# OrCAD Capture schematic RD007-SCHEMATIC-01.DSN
size A3
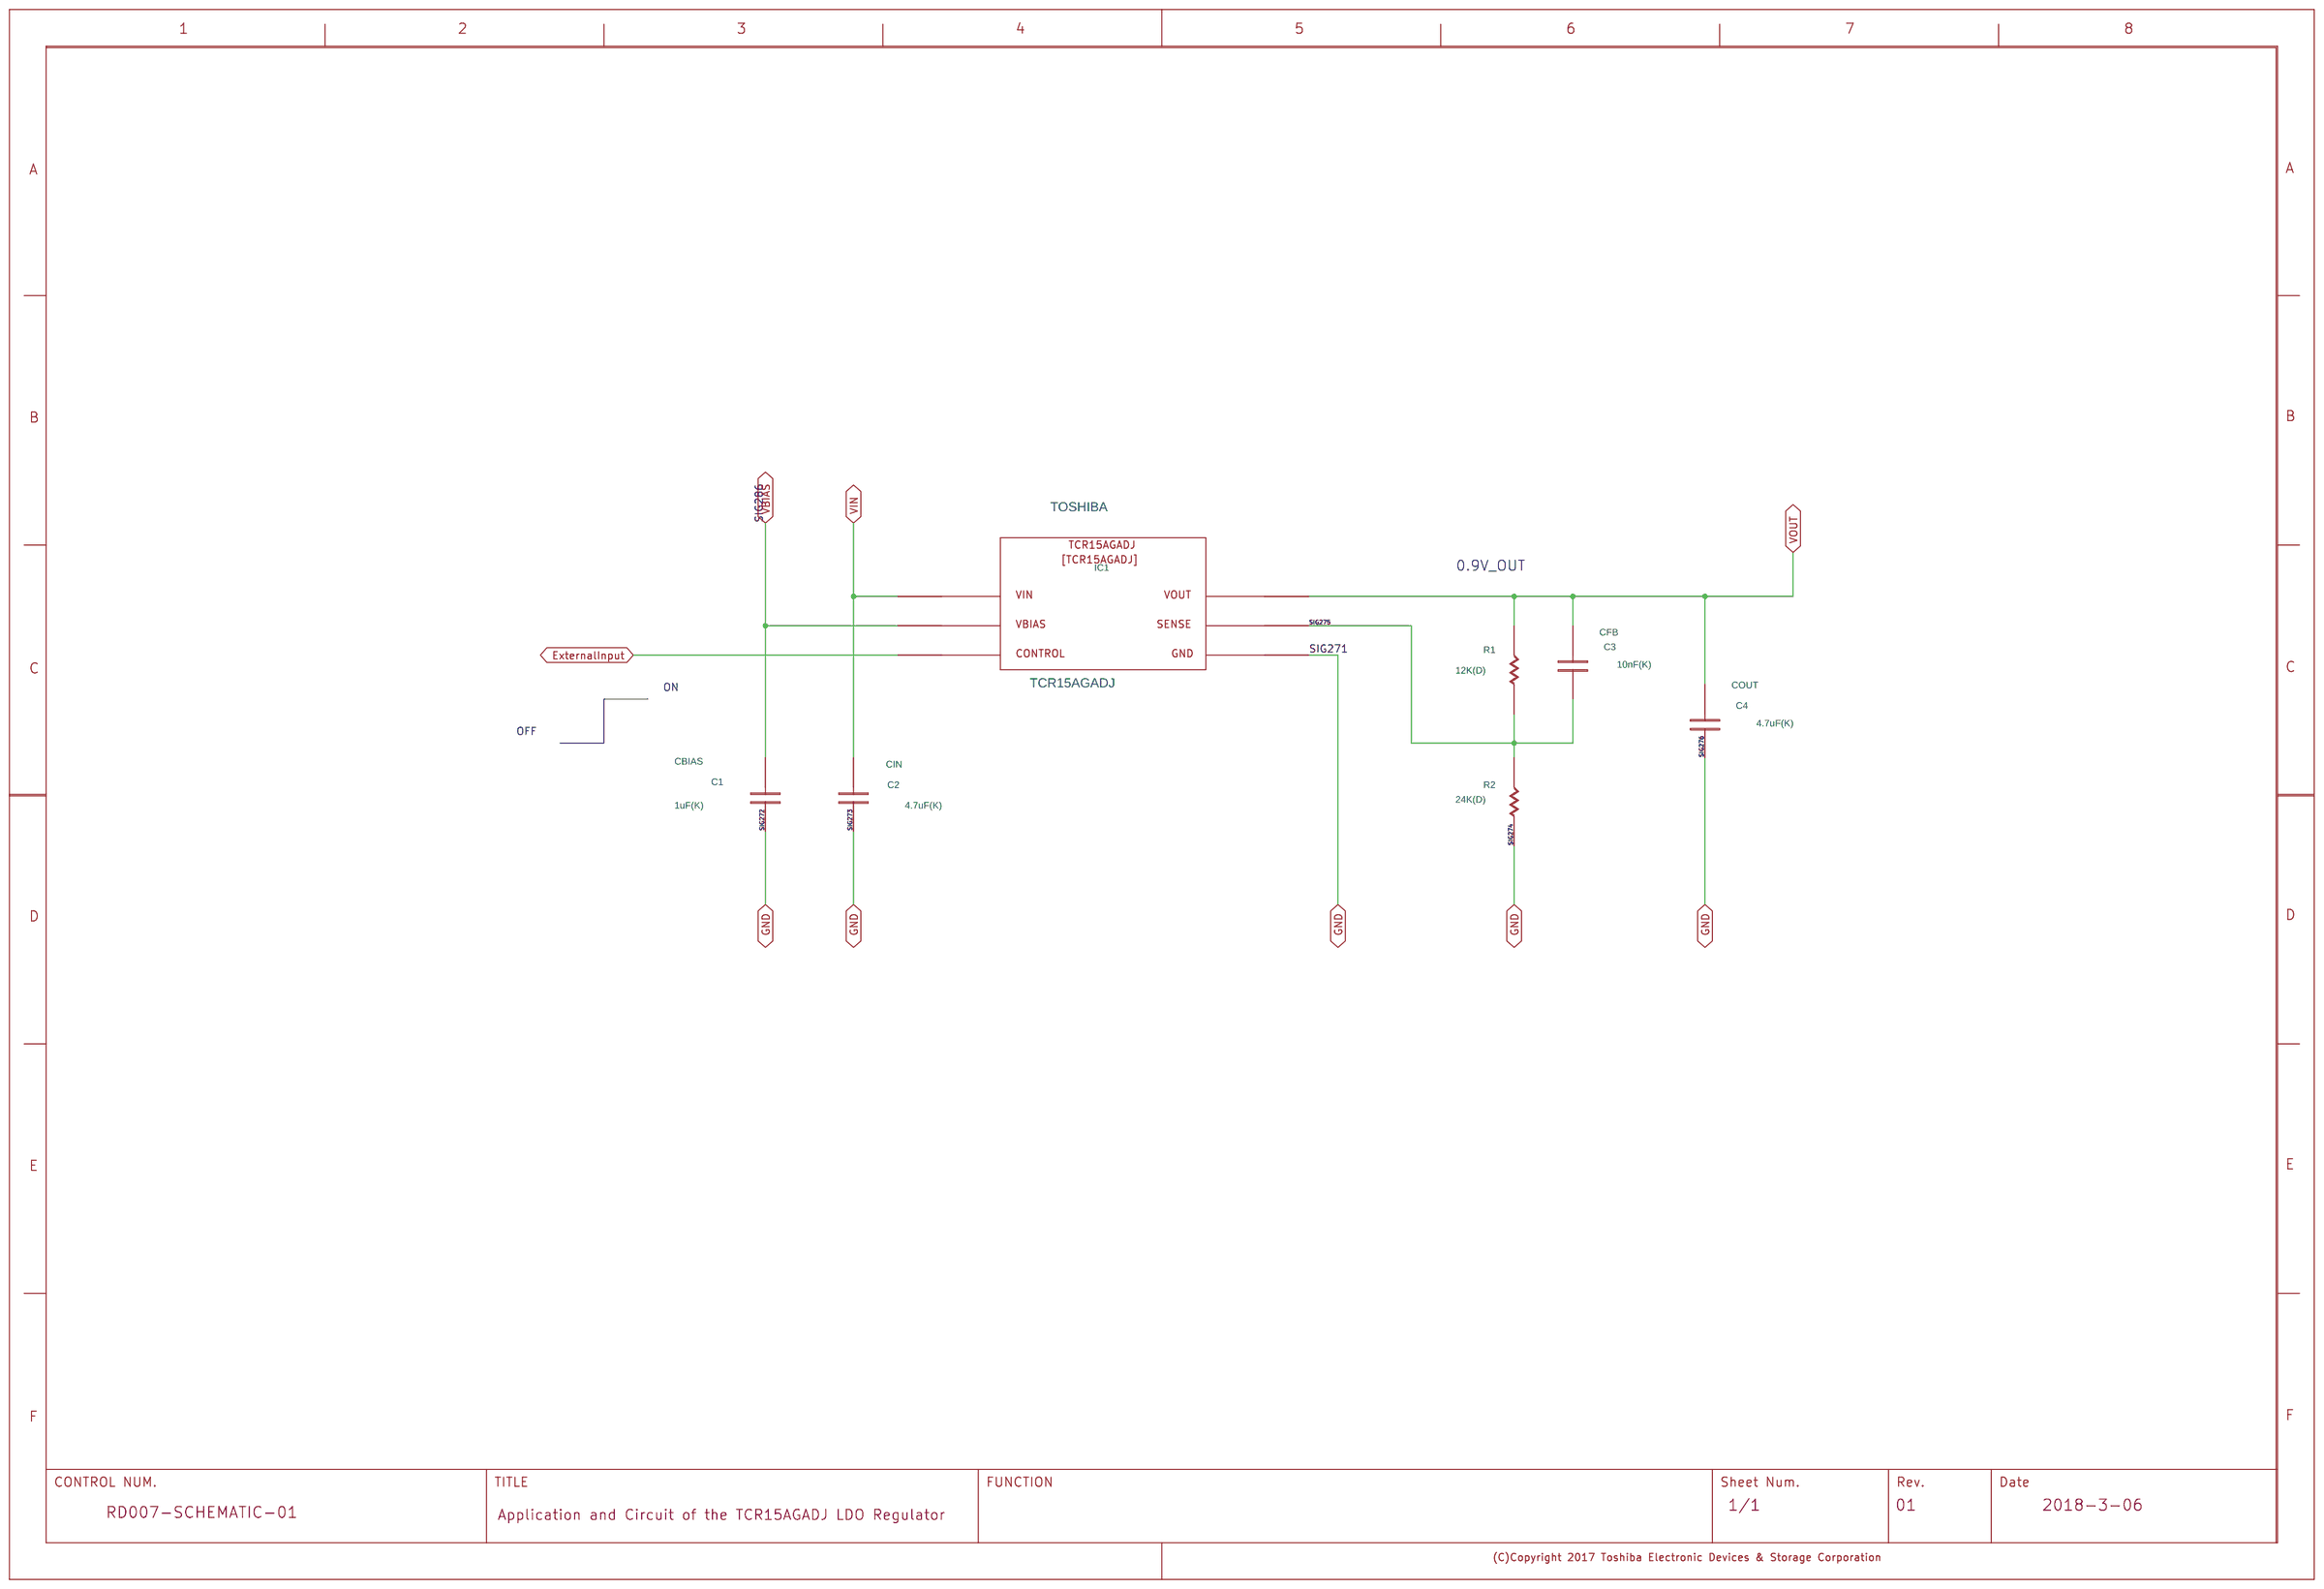
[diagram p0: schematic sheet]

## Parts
C1  C
C2  C
C3  C
C4  C
IC1  S-TCR15AGADJ
R1  R
R2  R
U?#1  WAKU_DEF100

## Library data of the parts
C1 = C: COMP: PRT_4; COMPCOMMENT: CBIAS; COMPONENTTYPE: 4; GCOUNT: 1; MAXGCOUNT: 1; SIZECODESMD: 1005; VAL1: 1uF(K); VAL2: 10V
C2 = C: COMP: PRT_5; COMPCOMMENT: CIN; COMPONENTTYPE: 4; GCOUNT: 1; MAXGCOUNT: 1; SIZECODESMD: 1608; VAL1: 4.7uF(K); VAL2: 10V
C3 = C: COMP: PRT_4; COMPCOMMENT: CFB; COMPONENTTYPE: 4; GCOUNT: 1; MAXGCOUNT: 1; SIZECODESMD: 1005; VAL1: 10nF(K); VAL2: 50V
C4 = C: COMP: PRT_5; COMPCOMMENT: COUT; COMPONENTTYPE: 4; GCOUNT: 1; MAXGCOUNT: 1; SIZECODESMD: 1608; VAL1: 4.7uF(K); VAL2: 10V
IC1 = S-TCR15AGADJ: COMP: PRT_1; COMPCOMMENT: TCR15AGADJ; COMPONENTTYPE: 4; USERCOMPTEXT3: TOSHIBA
R1 = R: COMP: PRT_2; COMPONENTTYPE: 4; GCOUNT: 1; MAXGCOUNT: 1; SIZECODESMD: 1005; VAL1: 12K(D); VAL2: 63mW
R2 = R: COMP: PRT_3; COMPONENTTYPE: 4; GCOUNT: 1; MAXGCOUNT: 1; SIZECODESMD: 1005; VAL1: 24K(D); VAL2: 63mW
U?#1 = WAKU_DEF100: COMPONENTTYPE: 2; DATE: 2018-3-06; DRAWINGNUMBER: RD007-SCHEMATIC-01; FUNCTION: Regulator(adjustable output voltage); REVISION: 01; SHEETNUMBER: 1/1; TITLE: Application and Circuit of the TCR15AGADJ LDO Regulator; UPDATEDATE: 2018/03/06; UPDATETIME: 16:05:37; UPDATEUSER: f1043010

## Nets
GND: C1.1 C2.1 C4.1 IC1.C1 R2.1
VIN: C2.2 IC1.A2
ExternalInput: IC1.B2
SIG275: C3.1 IC1.B1 R1.1 R2.2
VBIAS: C1.2 IC1.C2
VOUT: C3.2 C4.2 IC1.A1 R1.2

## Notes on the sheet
- 0.9V_OUT
- ON
- OFF
